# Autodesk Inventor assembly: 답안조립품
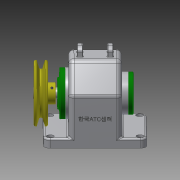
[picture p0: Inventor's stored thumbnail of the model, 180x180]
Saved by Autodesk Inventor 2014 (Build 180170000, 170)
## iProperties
Created: 2016-12
Part Number: 답안조립품
Document SubType Name: Assembly
Designer: 702
Author: 702
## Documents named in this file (15)
- C:\Users\702\Desktop\461207V1016\답안조립품.iam
- C:\Users\702\Desktop\461207V1016\본체.ipt
- C:\Users\702\Desktop\461207V1016\V-벨트풀리.ipt
- C:\Users\702\Desktop\461207V1016\뒤커버.ipt
- C:\Users\702\Desktop\461207V1016\멈춤나사 - M4x10.ipt
- C:\Users\702\Desktop\461207V1016\베어링 6203.ipt
- C:\Users\702\Desktop\461207V1016\볼트 M3 x 8.ipt
- C:\Users\702\Desktop\461207V1016\볼트 M3 x 10.ipt
- C:\Users\702\Desktop\461207V1016\부시.ipt
- C:\Users\702\Desktop\461207V1016\스퍼기어.ipt
- C:\Users\702\Desktop\461207V1016\앞커버.ipt
- C:\Users\702\Desktop\461207V1016\오일씰 28 40 8.ipt
- C:\Users\702\Desktop\461207V1016\축.ipt
- C:\Users\702\Desktop\461207V1016\키 - 5 x 5 x 18.ipt
- C:\Users\702\Desktop\461207V1016\키 - 6 x 6 x 22.ipt
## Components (9 placed, 3 different names)
1. V-벨트풀리:1
2. ISO 4762 M3 x 8:1
3. ISO 4762 M3 x 8:2
4. ISO 4762 M3 x 8:3
5. ISO 4762 M3 x 8:4
6. ISO 4762 M3 x 10:1
7. ISO 4762 M3 x 10:2
8. ISO 4762 M3 x 10:3
9. ISO 4762 M3 x 10:4
